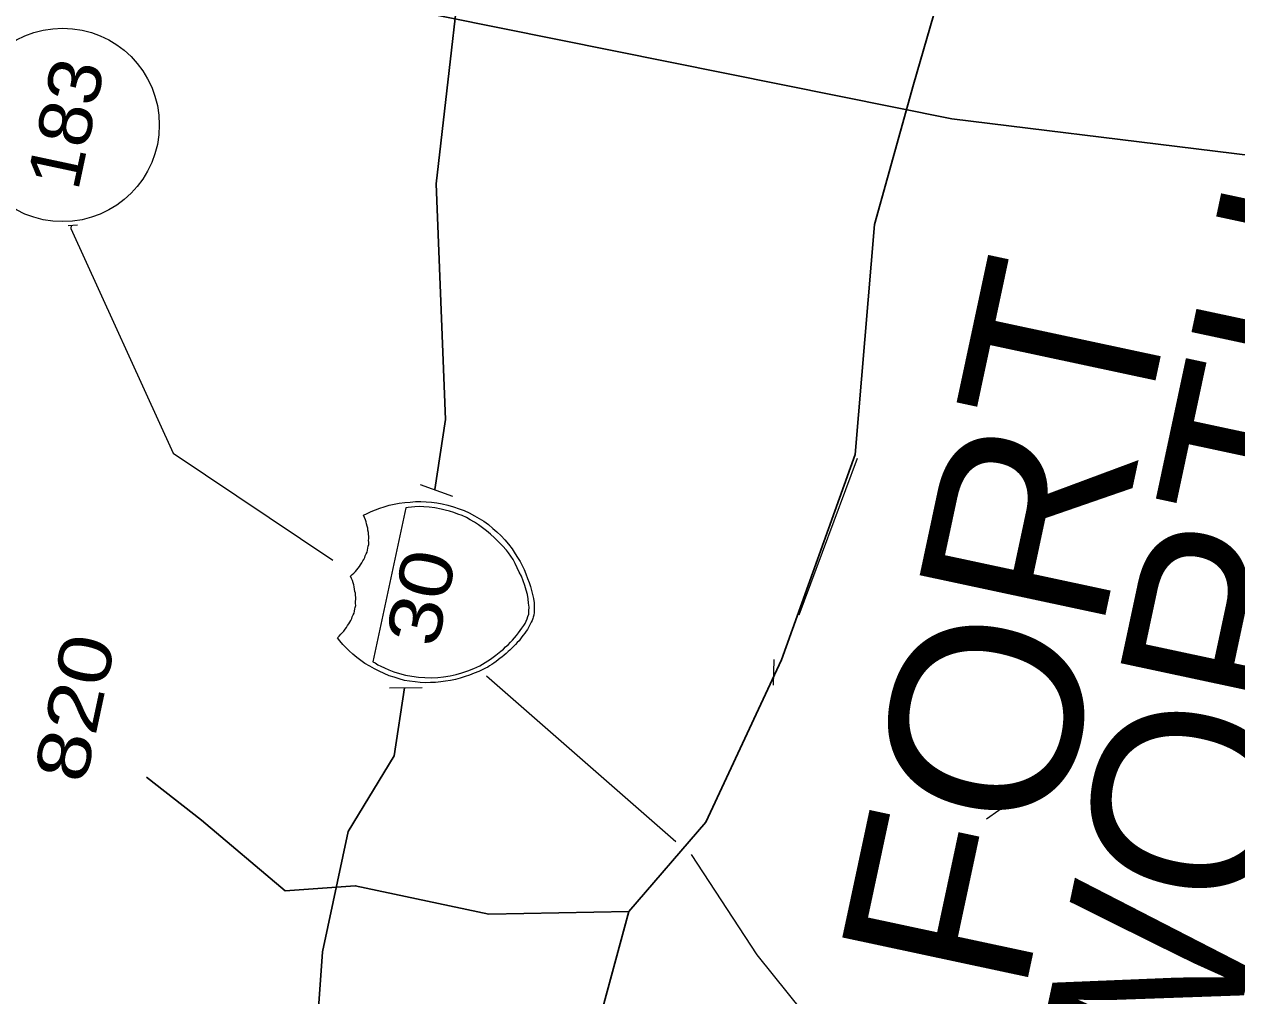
# Model space of a CAD drawing. Extents: x 2363411 to 2369126, y 6976878 to 6988319.
# Drawn here: x 2368256.8 to 2368374.1, y 6987907.5 to 6988001.5 of the extents above; entities that cross this region are included whole.
import ezdxf

# ---------------------------------------------------------------- set-up
doc = ezdxf.new("R2010")
doc.units = 0
doc.header["$LTSCALE"] = 2
doc.layers.add('62', color=7, linetype='Continuous', lineweight=13)
doc.layers.add('63', color=7, linetype='Continuous', lineweight=13)

msp = doc.modelspace()

# ---------------------------------------------------------------- linework, layer by layer
at = {"layer": '62'}
for p, q in [((2368261.009, 6987982.032), (2368261.892, 6987982.073)), ((2368261.282, 6987982.017), (2368261.27, 6987981.744)), ((2368337.392, 6987959.474), (2368331.733, 6987944.302)), ((2368295.092, 6987956.959), (2368298.205, 6987955.813)), ((2368329.292, 6987937.506), (2368329.364, 6987940)), ((2368301.507, 6987938.426), (2368319.823, 6987922.384)), ((2368292.102, 6987937.261), (2368295.261, 6987937.298)), ((2368352.31, 6987926.235), (2368349.9, 6987924.543))]:
    msp.add_line(p, q, dxfattribs=at)
at = {"layer": '62', "lineweight": 25}
for p, q in [((2368273.924, 6987924.441), (2368268.578, 6987928.618)), ((2368315.293, 6987915.601), (2368311.177, 6987900.533))]:
    msp.add_line(p, q, dxfattribs=at)
for points in [[(2368354.847, 6988086.071), (2368354.706, 6988078.095), (2368353.478, 6988068.142), (2368351.579, 6988054.188), (2368349.489, 6988044.419), (2368348.853, 6988037.238), (2368350.559, 6988031.767), (2368350.381, 6988021.564), (2368346.413, 6988008.054), (2368342.848, 6987995.677), (2368339.073, 6987982.102), (2368337.198, 6987959.861), (2368330.069, 6987939.962), (2368322.731, 6987924.248), (2368315.293, 6987915.601), (2368301.729, 6987915.346), (2368288.793, 6987918.11), (2368282.016, 6987917.625), (2368273.924, 6987924.441)], [(2368299.708, 6988032.302), (2368299.958, 6988015.057), (2368296.639, 6987986.06), (2368297.535, 6987963.227), (2368296.503, 6987956.453)], [(2368243.911, 6988012.604), (2368291.866, 6988003.347), (2368346.556, 6987992.355), (2368417.518, 6987983.635), (2368451.697, 6987993.151)], [(2368293.576, 6987937.267), (2368292.564, 6987930.694), (2368288.12, 6987923.36), (2368285.632, 6987911.721), (2368283.768, 6987885.334)]]:
    msp.add_lwpolyline(points, dxfattribs=at)
at = {"layer": '62'}
for points in [[(2368261.27, 6987981.744), (2368271.182, 6987959.976), (2368286.619, 6987949.614)], [(2368288.952, 6987948.679), (2368289.082, 6987948.858), (2368289.206, 6987949.016), (2368289.311, 6987949.177), (2368289.441, 6987949.356), (2368289.528, 6987949.546), (2368289.625, 6987949.687), (2368289.711, 6987949.873), (2368289.772, 6987950.044), (2368289.858, 6987950.232), (2368289.94, 6987950.401), (2368289.983, 6987950.598), (2368290.025, 6987950.796), (2368290.063, 6987950.972), (2368290.099, 6987951.146), (2368290.096, 6987951.355), (2368290.092, 6987951.54), (2368290.106, 6987951.721), (2368290.105, 6987951.93), (2368290.076, 6987952.121), (2368290.07, 6987952.306), (2368290.026, 6987952.522), (2368290, 6987952.734), (2368289.95, 6987952.929), (2368289.9, 6987953.125), (2368289.847, 6987953.319), (2368289.777, 6987953.518), (2368289.691, 6987953.767), (2368289.598, 6987953.971), (2368289.956, 6987954.146), (2368290.346, 6987954.341), (2368290.747, 6987954.507), (2368291.17, 6987954.648), (2368291.612, 6987954.782), (2368292.082, 6987954.938), (2368292.565, 6987955.039), (2368293.046, 6987955.145), (2368293.587, 6987955.191), (2368294.103, 6987955.24), (2368294.619, 6987955.291), (2368295.149, 6987955.295), (2368295.674, 6987955.272), (2368296.194, 6987955.231), (2368296.687, 6987955.17), (2368297.22, 6987955.079), (2368297.745, 6987954.944), (2368298.307, 6987954.779), (2368298.842, 6987954.595), (2368299.334, 6987954.421), (2368299.839, 6987954.2), (2368300.329, 6987953.91), (2368300.782, 6987953.651), (2368301.254, 6987953.391), (2368301.692, 6987953.068), (2368302.119, 6987952.699), (2368302.507, 6987952.36), (2368302.91, 6987951.98), (2368303.281, 6987951.575), (2368303.63, 6987951.157), (2368303.972, 6987950.716), (2368304.285, 6987950.234), (2368304.505, 6987949.866), (2368304.747, 6987949.491), (2368304.963, 6987949.099), (2368305.157, 6987948.712), (2368305.318, 6987948.287), (2368305.479, 6987947.862), (2368305.624, 6987947.463), (2368305.769, 6987947.064), (2368305.869, 6987946.674), (2368305.97, 6987946.285), (2368306.049, 6987945.9), (2368306.103, 6987945.498), (2368306.107, 6987945.196), (2368306.124, 6987944.849), (2368306.107, 6987944.554), (2368306.072, 6987944.285)], [(2368306.072, 6987944.285), (2368306.015, 6987944.113), (2368305.98, 6987943.961), (2368305.917, 6987943.766), (2368305.838, 6987943.621), (2368305.762, 6987943.476), (2368305.675, 6987943.29), (2368305.568, 6987943.104), (2368305.459, 6987942.919), (2368305.329, 6987942.74), (2368305.222, 6987942.559), (2368305.063, 6987942.359), (2368304.937, 6987942.202), (2368304.804, 6987942.004), (2368304.65, 6987941.828), (2368304.475, 6987941.657), (2368304.319, 6987941.463), (2368304.145, 6987941.29), (2368303.965, 6987941.099), (2368303.764, 6987940.913), (2368303.595, 6987940.765), (2368303.42, 6987940.596), (2368303.201, 6987940.432), (2368303.002, 6987940.246), (2368302.814, 6987940.126), (2368302.618, 6987939.961), (2368302.426, 6987939.818), (2368302.21, 6987939.658), (2368302.02, 6987939.537), (2368301.807, 6987939.399), (2368301.62, 6987939.277), (2368301.416, 6987939.181), (2368301.207, 6987939.067), (2368300.773, 6987938.859), (2368300.32, 6987938.679), (2368299.866, 6987938.5), (2368299.424, 6987938.361), (2368298.953, 6987938.211), (2368298.49, 6987938.081), (2368298.028, 6987937.971), (2368297.528, 6987937.895), (2368297.078, 6987937.832), (2368296.558, 6987937.779), (2368296.076, 6987937.77), (2368295.59, 6987937.757), (2368295.085, 6987937.773), (2368294.593, 6987937.831), (2368294.056, 6987937.901), (2368293.568, 6987937.981), (2368293.048, 6987938.139), (2368292.573, 6987938.285), (2368292.078, 6987938.438), (2368291.594, 6987938.654), (2368291.111, 6987938.876), (2368290.656, 6987939.11), (2368290.204, 6987939.368), (2368289.732, 6987939.629), (2368289.334, 6987939.922), (2368288.936, 6987940.214), (2368288.565, 6987940.522), (2368288.222, 6987940.849), (2368287.898, 6987941.174), (2368287.594, 6987941.47), (2368287.319, 6987941.803), (2368287.065, 6987942.111), (2368287.239, 6987942.28), (2368287.413, 6987942.449), (2368287.564, 6987942.626), (2368287.687, 6987942.759), (2368287.817, 6987942.938), (2368287.941, 6987943.097), (2368288.05, 6987943.283), (2368288.178, 6987943.46), (2368288.261, 6987943.626), (2368288.367, 6987943.788), (2368288.451, 6987943.976), (2368288.511, 6987944.147), (2368288.597, 6987944.338), (2368288.68, 6987944.504), (2368288.717, 6987944.68), (2368288.764, 6987944.901), (2368288.797, 6987945.056), (2368288.839, 6987945.249), (2368288.832, 6987945.439), (2368288.831, 6987945.644), (2368288.847, 6987945.824), (2368288.842, 6987946.01), (2368288.816, 6987946.224), (2368288.815, 6987946.43), (2368288.76, 6987946.604), (2368288.738, 6987946.815), (2368288.69, 6987947.032), (2368288.644, 6987947.248), (2368288.592, 6987947.423), (2368288.52, 6987947.643), (2368288.426, 6987947.847), (2368288.339, 6987948.074), (2368288.507, 6987948.222), (2368288.673, 6987948.348), (2368288.824, 6987948.523), (2368288.952, 6987948.679)], [(2368321.306, 6987921.123), (2368327.674, 6987911.412), (2368333.595, 6987904.027), (2368343.223, 6987888.761), (2368353.927, 6987874.579)]]:
    msp.add_lwpolyline(points, dxfattribs=at)
msp.add_lwpolyline([(2368293.684, 6987954.683), (2368290.501, 6987939.787), (2368290.709, 6987939.674), (2368290.969, 6987939.503), (2368291.259, 6987939.349), (2368291.641, 6987939.2), (2368292.057, 6987938.995), (2368292.545, 6987938.799), (2368293.065, 6987938.64), (2368293.674, 6987938.486), (2368294.275, 6987938.382), (2368294.921, 6987938.291), (2368295.535, 6987938.252), (2368296.151, 6987938.235), (2368296.778, 6987938.262), (2368297.344, 6987938.325), (2368297.985, 6987938.417), (2368298.567, 6987938.547), (2368299.128, 6987938.703), (2368299.701, 6987938.904), (2368300.276, 6987939.126), (2368300.842, 6987939.396), (2368301.371, 6987939.721), (2368301.9, 6987940.047), (2368302.393, 6987940.423), (2368302.895, 6987940.823), (2368303.138, 6987941), (2368303.349, 6987941.231), (2368303.601, 6987941.431), (2368303.815, 6987941.683), (2368304.015, 6987941.872), (2368304.227, 6987942.103), (2368304.414, 6987942.339), (2368304.606, 6987942.596), (2368304.77, 6987942.815), (2368304.936, 6987943.055), (2368305.102, 6987943.296), (2368305.237, 6987943.498), (2368305.355, 6987943.727), (2368305.445, 6987943.935), (2368305.519, 6987944.172), (2368305.589, 6987944.388), (2368305.609, 6987944.703), (2368305.647, 6987945.088), (2368305.584, 6987945.447), (2368305.543, 6987945.893), (2368305.467, 6987946.3), (2368305.328, 6987946.723), (2368305.213, 6987947.16), (2368305.056, 6987947.607), (2368304.878, 6987948.062), (2368304.667, 6987948.471), (2368304.479, 6987948.881), (2368304.267, 6987949.295), (2368304.073, 6987949.682), (2368303.868, 6987950.002), (2368303.637, 6987950.327), (2368303.436, 6987950.577), (2368303.046, 6987951.006), (2368302.671, 6987951.407), (2368302.292, 6987951.789), (2368301.887, 6987952.149), (2368301.515, 6987952.46), (2368301.119, 6987952.753), (2368300.741, 6987953.038), (2368300.336, 6987953.286), (2368299.929, 6987953.535), (2368299.559, 6987953.751), (2368299.138, 6987953.933), (2368298.735, 6987954.091), (2368298.325, 6987954.223), (2368297.921, 6987954.379), (2368297.503, 6987954.466), (2368297.114, 6987954.574), (2368296.493, 6987954.684), (2368295.955, 6987954.752), (2368295.433, 6987954.794), (2368294.98, 6987954.821), (2368294.56, 6987954.797), (2368294.23, 6987954.753), (2368293.924, 6987954.728)], close=True, dxfattribs=at)
msp.add_circle((2368260.466, 6987991.756), 9.364, dxfattribs=at)
at = {"layer": '63'}
for p, q in [((2368261.009, 6987982.032), (2368261.892, 6987982.073)), ((2368261.282, 6987982.017), (2368261.27, 6987981.744)), ((2368337.392, 6987959.474), (2368331.733, 6987944.302)), ((2368295.092, 6987956.959), (2368298.205, 6987955.813)), ((2368329.292, 6987937.506), (2368329.364, 6987940)), ((2368301.507, 6987938.426), (2368319.823, 6987922.384)), ((2368292.102, 6987937.261), (2368295.261, 6987937.298)), ((2368352.31, 6987926.235), (2368349.9, 6987924.543))]:
    msp.add_line(p, q, dxfattribs=at)
at = {"layer": '63', "lineweight": 25}
for p, q in [((2368273.924, 6987924.441), (2368268.578, 6987928.618)), ((2368315.293, 6987915.601), (2368311.177, 6987900.533))]:
    msp.add_line(p, q, dxfattribs=at)
for points in [[(2368354.847, 6988086.071), (2368354.706, 6988078.095), (2368353.478, 6988068.142), (2368351.579, 6988054.188), (2368349.489, 6988044.419), (2368348.853, 6988037.238), (2368350.559, 6988031.767), (2368350.381, 6988021.564), (2368346.413, 6988008.054), (2368342.848, 6987995.677), (2368339.073, 6987982.102), (2368337.198, 6987959.861), (2368330.069, 6987939.962), (2368322.731, 6987924.248), (2368315.293, 6987915.601), (2368301.729, 6987915.346), (2368288.793, 6987918.11), (2368282.016, 6987917.625), (2368273.924, 6987924.441)], [(2368299.708, 6988032.302), (2368299.958, 6988015.057), (2368296.639, 6987986.06), (2368297.535, 6987963.227), (2368296.503, 6987956.453)], [(2368243.911, 6988012.604), (2368291.866, 6988003.347), (2368346.556, 6987992.355), (2368417.518, 6987983.635), (2368451.697, 6987993.151)], [(2368293.576, 6987937.267), (2368292.564, 6987930.694), (2368288.12, 6987923.36), (2368285.632, 6987911.721), (2368283.768, 6987885.334)]]:
    msp.add_lwpolyline(points, dxfattribs=at)
at = {"layer": '63'}
for points in [[(2368261.27, 6987981.744), (2368271.182, 6987959.976), (2368286.619, 6987949.614)], [(2368288.952, 6987948.679), (2368289.082, 6987948.858), (2368289.206, 6987949.016), (2368289.311, 6987949.177), (2368289.441, 6987949.356), (2368289.528, 6987949.546), (2368289.625, 6987949.687), (2368289.711, 6987949.873), (2368289.772, 6987950.044), (2368289.858, 6987950.232), (2368289.94, 6987950.401), (2368289.983, 6987950.598), (2368290.025, 6987950.796), (2368290.063, 6987950.972), (2368290.099, 6987951.146), (2368290.096, 6987951.355), (2368290.092, 6987951.54), (2368290.106, 6987951.721), (2368290.105, 6987951.93), (2368290.076, 6987952.121), (2368290.07, 6987952.306), (2368290.026, 6987952.522), (2368290, 6987952.734), (2368289.95, 6987952.929), (2368289.9, 6987953.125), (2368289.847, 6987953.319), (2368289.777, 6987953.518), (2368289.691, 6987953.767), (2368289.598, 6987953.971), (2368289.956, 6987954.146), (2368290.346, 6987954.341), (2368290.747, 6987954.507), (2368291.17, 6987954.648), (2368291.612, 6987954.782), (2368292.082, 6987954.938), (2368292.565, 6987955.039), (2368293.046, 6987955.145), (2368293.587, 6987955.191), (2368294.103, 6987955.24), (2368294.619, 6987955.291), (2368295.149, 6987955.295), (2368295.674, 6987955.272), (2368296.194, 6987955.231), (2368296.687, 6987955.17), (2368297.22, 6987955.079), (2368297.745, 6987954.944), (2368298.307, 6987954.779), (2368298.842, 6987954.595), (2368299.334, 6987954.421), (2368299.839, 6987954.2), (2368300.329, 6987953.91), (2368300.782, 6987953.651), (2368301.254, 6987953.391), (2368301.692, 6987953.068), (2368302.119, 6987952.699), (2368302.507, 6987952.36), (2368302.91, 6987951.98), (2368303.281, 6987951.575), (2368303.63, 6987951.157), (2368303.972, 6987950.716), (2368304.285, 6987950.234), (2368304.505, 6987949.866), (2368304.747, 6987949.491), (2368304.963, 6987949.099), (2368305.157, 6987948.712), (2368305.318, 6987948.287), (2368305.479, 6987947.862), (2368305.624, 6987947.463), (2368305.769, 6987947.064), (2368305.869, 6987946.674), (2368305.97, 6987946.285), (2368306.049, 6987945.9), (2368306.103, 6987945.498), (2368306.107, 6987945.196), (2368306.124, 6987944.849), (2368306.107, 6987944.554), (2368306.072, 6987944.285)], [(2368306.072, 6987944.285), (2368306.015, 6987944.113), (2368305.98, 6987943.961), (2368305.917, 6987943.766), (2368305.838, 6987943.621), (2368305.762, 6987943.476), (2368305.675, 6987943.29), (2368305.568, 6987943.104), (2368305.459, 6987942.919), (2368305.329, 6987942.74), (2368305.222, 6987942.559), (2368305.063, 6987942.359), (2368304.937, 6987942.202), (2368304.804, 6987942.004), (2368304.65, 6987941.828), (2368304.475, 6987941.657), (2368304.319, 6987941.463), (2368304.145, 6987941.29), (2368303.965, 6987941.099), (2368303.764, 6987940.913), (2368303.595, 6987940.765), (2368303.42, 6987940.596), (2368303.201, 6987940.432), (2368303.002, 6987940.246), (2368302.814, 6987940.126), (2368302.618, 6987939.961), (2368302.426, 6987939.818), (2368302.21, 6987939.658), (2368302.02, 6987939.537), (2368301.807, 6987939.399), (2368301.62, 6987939.277), (2368301.416, 6987939.181), (2368301.207, 6987939.067), (2368300.773, 6987938.859), (2368300.32, 6987938.679), (2368299.866, 6987938.5), (2368299.424, 6987938.361), (2368298.953, 6987938.211), (2368298.49, 6987938.081), (2368298.028, 6987937.971), (2368297.528, 6987937.895), (2368297.078, 6987937.832), (2368296.558, 6987937.779), (2368296.076, 6987937.77), (2368295.59, 6987937.757), (2368295.085, 6987937.773), (2368294.593, 6987937.831), (2368294.056, 6987937.901), (2368293.568, 6987937.981), (2368293.048, 6987938.139), (2368292.573, 6987938.285), (2368292.078, 6987938.438), (2368291.594, 6987938.654), (2368291.111, 6987938.876), (2368290.656, 6987939.11), (2368290.204, 6987939.368), (2368289.732, 6987939.629), (2368289.334, 6987939.922), (2368288.936, 6987940.214), (2368288.565, 6987940.522), (2368288.222, 6987940.849), (2368287.898, 6987941.174), (2368287.594, 6987941.47), (2368287.319, 6987941.803), (2368287.065, 6987942.111), (2368287.239, 6987942.28), (2368287.413, 6987942.449), (2368287.564, 6987942.626), (2368287.687, 6987942.759), (2368287.817, 6987942.938), (2368287.941, 6987943.097), (2368288.05, 6987943.283), (2368288.178, 6987943.46), (2368288.261, 6987943.626), (2368288.367, 6987943.788), (2368288.451, 6987943.976), (2368288.511, 6987944.147), (2368288.597, 6987944.338), (2368288.68, 6987944.504), (2368288.717, 6987944.68), (2368288.764, 6987944.901), (2368288.797, 6987945.056), (2368288.839, 6987945.249), (2368288.832, 6987945.439), (2368288.831, 6987945.644), (2368288.847, 6987945.824), (2368288.842, 6987946.01), (2368288.816, 6987946.224), (2368288.815, 6987946.43), (2368288.76, 6987946.604), (2368288.738, 6987946.815), (2368288.69, 6987947.032), (2368288.644, 6987947.248), (2368288.592, 6987947.423), (2368288.52, 6987947.643), (2368288.426, 6987947.847), (2368288.339, 6987948.074), (2368288.507, 6987948.222), (2368288.673, 6987948.348), (2368288.824, 6987948.523), (2368288.952, 6987948.679)], [(2368321.306, 6987921.123), (2368327.674, 6987911.412), (2368333.595, 6987904.027), (2368343.223, 6987888.761), (2368353.927, 6987874.579)]]:
    msp.add_lwpolyline(points, dxfattribs=at)
msp.add_lwpolyline([(2368293.684, 6987954.683), (2368290.501, 6987939.787), (2368290.709, 6987939.674), (2368290.969, 6987939.503), (2368291.259, 6987939.349), (2368291.641, 6987939.2), (2368292.057, 6987938.995), (2368292.545, 6987938.799), (2368293.065, 6987938.64), (2368293.674, 6987938.486), (2368294.275, 6987938.382), (2368294.921, 6987938.291), (2368295.535, 6987938.252), (2368296.151, 6987938.235), (2368296.778, 6987938.262), (2368297.344, 6987938.325), (2368297.985, 6987938.417), (2368298.567, 6987938.547), (2368299.128, 6987938.703), (2368299.701, 6987938.904), (2368300.276, 6987939.126), (2368300.842, 6987939.396), (2368301.371, 6987939.721), (2368301.9, 6987940.047), (2368302.393, 6987940.423), (2368302.895, 6987940.823), (2368303.138, 6987941), (2368303.349, 6987941.231), (2368303.601, 6987941.431), (2368303.815, 6987941.683), (2368304.015, 6987941.872), (2368304.227, 6987942.103), (2368304.414, 6987942.339), (2368304.606, 6987942.596), (2368304.77, 6987942.815), (2368304.936, 6987943.055), (2368305.102, 6987943.296), (2368305.237, 6987943.498), (2368305.355, 6987943.727), (2368305.445, 6987943.935), (2368305.519, 6987944.172), (2368305.589, 6987944.388), (2368305.609, 6987944.703), (2368305.647, 6987945.088), (2368305.584, 6987945.447), (2368305.543, 6987945.893), (2368305.467, 6987946.3), (2368305.328, 6987946.723), (2368305.213, 6987947.16), (2368305.056, 6987947.607), (2368304.878, 6987948.062), (2368304.667, 6987948.471), (2368304.479, 6987948.881), (2368304.267, 6987949.295), (2368304.073, 6987949.682), (2368303.868, 6987950.002), (2368303.637, 6987950.327), (2368303.436, 6987950.577), (2368303.046, 6987951.006), (2368302.671, 6987951.407), (2368302.292, 6987951.789), (2368301.887, 6987952.149), (2368301.515, 6987952.46), (2368301.119, 6987952.753), (2368300.741, 6987953.038), (2368300.336, 6987953.286), (2368299.929, 6987953.535), (2368299.559, 6987953.751), (2368299.138, 6987953.933), (2368298.735, 6987954.091), (2368298.325, 6987954.223), (2368297.921, 6987954.379), (2368297.503, 6987954.466), (2368297.114, 6987954.574), (2368296.493, 6987954.684), (2368295.955, 6987954.752), (2368295.433, 6987954.794), (2368294.98, 6987954.821), (2368294.56, 6987954.797), (2368294.23, 6987954.753), (2368293.924, 6987954.728)], close=True, dxfattribs=at)
msp.add_circle((2368260.466, 6987991.756), 9.364, dxfattribs=at)

# ---------------------------------------------------------------- texts
at = {"layer": '62'}
for s, height, width, p in [('183', 5.099, 1.1, (2368261.947, 6987985.238)), ('FORT', 18.39, 1.05, (2368353.486, 6987907.186)), ('30', 5.099, 1.2, (2368296.705, 6987941.042)), ('820', 5.099, 1.25, (2368262.641, 6987927.863))]:
    msp.add_text(s, height=height, rotation=77.939, dxfattribs=dict(at, width=width)).set_placement(p)
msp.add_text('WORTH', height=18.39, rotation=77.939, dxfattribs=at).set_placement((2368371.617, 6987892.428))
at = {"layer": '63'}
for s, height, width, p in [('183', 5.099, 1.1, (2368261.947, 6987985.238)), ('FORT', 18.39, 1.05, (2368353.486, 6987907.186)), ('30', 5.099, 1.2, (2368296.705, 6987941.042)), ('820', 5.099, 1.25, (2368262.641, 6987927.863))]:
    msp.add_text(s, height=height, rotation=77.939, dxfattribs=dict(at, width=width)).set_placement(p)
msp.add_text('WORTH', height=18.39, rotation=77.939, dxfattribs=at).set_placement((2368371.617, 6987892.428))

doc.saveas('drawing.dxf')
